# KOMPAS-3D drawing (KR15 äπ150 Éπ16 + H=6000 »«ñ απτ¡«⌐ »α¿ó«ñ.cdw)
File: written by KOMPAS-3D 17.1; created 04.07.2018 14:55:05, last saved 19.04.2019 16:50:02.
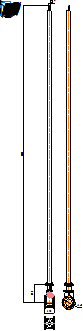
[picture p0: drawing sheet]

Sheet 1: A4, portrait

Title block, sheet 1: name: KR15 Ду150 Ру16 + / H=6000 под ручной привод; material: Внимание! Данный продукт является объектом авторского права ООО «Торговый Дом АДЛ». / Запрещается изменение, копирование, распространение / (в том числе путем копирования на другие сайты и ресурсы в Интернете) / или любое иное использование информации и объектов без предварительного / согласия правообладателя (ООО «Торговый Дом АДЛ»).; mass: 36,7; sheets: 1; organisation: ООО "Торговый дом АДЛ"; sheet format: A4; stored path: \\adlc.lan\data\АДЛ_ПКД\3D-модели\ADL production\Клиновые задвижки серии KR ГРАНАР\Клиновые задвижки KR15 со стационарным удлинением\KOMPAS 2D\KR15 Ду150 Ру16 + H=6000 под ручной привод.cdw

Views: Проекционный вид 6, Проекционный вид 12, Проекционный вид 14
Referenced files in C:\Users\kka\KOMPAS_Work\!Trash\ГРАНАР KR Задвижки с приводами и удлинениями\С приводами\: KR15 Ду150 Ру16.m3d
Referenced files in C:\Users\kka\KOMPAS_Work\Удлинения БИВАЛ ф. ADL\!Задвижки\У_ду_125-400\: Ушду125-400.a3d
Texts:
  kka
  adl
  УШКЗ.100000.00.00
  Удлинение клиновой задвижки с редуктором
  Крепежное изделие ГОСТ
  Болт
  ГОСТ
  Гайка
  Лит-Масса-Масштаб
  Материал-Предприятие
  Title Specification
  Body Specification ( left align )
  Body Specificaton ( centered )
  Поз.
  Кол.
  Приме-
  чание
  Таблица спецификации
Dimensions and other numbers on the sheet: 6000; 370; 210; 27; 4; 1; 58; 40Х; 019; 1:1; 36,7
